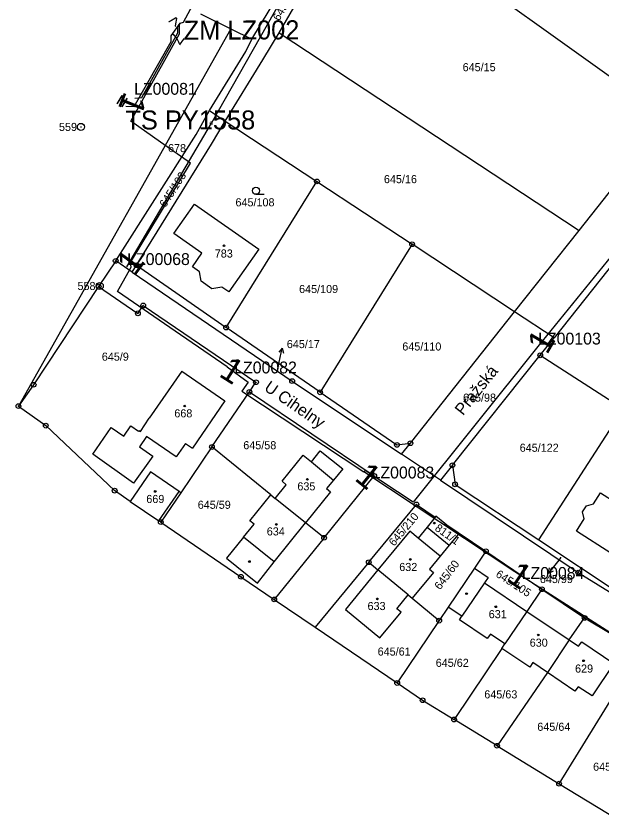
# Model space of a CAD drawing. Extents: x -738131 to -734179, y -1033447 to -1030078.
# Drawn here: x -736294.6 to -736171.2, y -1032867.6 to -1032698.6 of the extents above; entities that cross this region are included whole.
import ezdxf

# ---------------------------------------------------------------- set-up
doc = ezdxf.new("R2010")
doc.units = 0
for name, color, linetype in [('ftf_2010', 7, 'Continuous'), ('ftf_2050', 7, 'Continuous'), ('ftf_2060', 7, 'Continuous'), ('ftf_3010', 7, 'Continuous'), ('ftf_3010_ftf_3010_gtda_3015_gtda_3015_1', 7, 'Continuous'), ('ftf_3150', 7, 'Continuous'), ('ftf_3150_ftf_3150_gtda_3155_gtda_3155_1', 7, 'Continuous'), ('ftf_3160', 7, 'Continuous'), ('ftf_3160_ftf_3160_gtda_3165_gtda_3165_1', 7, 'Continuous'), ('ftf_3170', 7, 'Continuous'), ('ftf_3240', 7, 'Continuous'), ('ftf_nu', 7, 'Continuous'), ('Vrstva 1', 7, 'Continuous'), ('Vrstva 2', 7, 'Continuous'), ('Vrstva 3', 7, 'Continuous'), ('Vrstva 4', 7, 'Continuous'), ('Vrstva 5', 7, 'Continuous'), ('Vrstva 7', 7, 'Continuous'), ('Vrstva 8', 7, 'Continuous')]:
    doc.layers.add(name, color=color, linetype=linetype)

msp = doc.modelspace()

# ---------------------------------------------------------------- linework, layer by layer
at = {"layer": 'ftf_2010'}
for points in [[(-736260.08, -1032700.09), (-736259.36, -1032699.83), (-736255.9, -1032693.4)], [(-736250.19, -1032772.44), (-736261.12, -1032764.89), (-736273.29, -1032756.56), (-736270.36, -1032751.45), (-736270.49, -1032750.48), (-736257.9, -1032729.52), (-736264.19, -1032725.12), (-736270.47, -1032720.72), (-736260.17, -1032702.28), (-736260.17, -1032700.42), (-736260.08, -1032700.09)], [(-736269.58, -1032715.86), (-736268.12, -1032715.71), (-736260.53, -1032702.12), (-736260.53, -1032700.85), (-736260.08, -1032700.09)], [(-736167.34, -1032747.62), (-736168.31, -1032747.92), (-736184.73, -1032768.17)], [(-736184.73, -1032768.17), (-736210.99, -1032800.91), (-736221.08, -1032794.29), (-736221.41, -1032794.56)], [(-736250.19, -1032772.44), (-736245.76, -1032775.68), (-736247.06, -1032777.59), (-736221.41, -1032794.56)], [(-736189.57, -1032815.57), (-736221.41, -1032794.56)], [(-736158.51, -1032835.5), (-736189.57, -1032815.57)]]:
    msp.add_lwpolyline(points, dxfattribs=at)
at = {"layer": 'ftf_2050'}
msp.add_lwpolyline([(-736271.31, -1032751.37), (-736253.49, -1032721.14), (-736231.33, -1032682.11)], dxfattribs=at)
at = {"layer": 'ftf_2060'}
msp.add_lwpolyline([(-736271.48, -1032717.58), (-736269.72, -1032717.63), (-736261.98, -1032703.91), (-736261.98, -1032702.76), (-736260.08, -1032700.09)], dxfattribs=at)
at = {"layer": 'Vrstva 1'}
for points in [[(-736165.79, -1032714.02), (-736208.22, -1032683.61)], [(-736244.97, -1032703.43), (-736236.07, -1032688.6)], [(-736239.18, -1032702.09), (-736232.56, -1032690.52)], [(-736255.81, -1032698.1), (-736249.41, -1032701.25)], [(-736249.41, -1032701.25), (-736294.12, -1032780.7)], [(-736249.41, -1032701.25), (-736244.97, -1032703.43)], [(-736242.67, -1032707.79), (-736239.18, -1032702.09)], [(-736239.18, -1032702.09), (-736176.04, -1032743.72)], [(-736246.25, -1032706.01), (-736244.97, -1032703.43)], [(-736253.9, -1032718.47), (-736246.25, -1032706.01)], [(-736250.56, -1032720.67), (-736242.67, -1032707.79)], [(-736256.7, -1032723.54), (-736253.9, -1032718.47)], [(-736253.9, -1032718.47), (-736250.56, -1032720.67)], [(-736176.04, -1032743.72), (-736157.13, -1032719.88)], [(-736253.46, -1032725.57), (-736250.56, -1032720.67)], [(-736250.56, -1032720.67), (-736231.25, -1032733.4)], [(-736273.64, -1032750.13), (-736256.7, -1032723.54)], [(-736269.28, -1032751.04), (-736253.46, -1032725.57)], [(-736250.38, -1032764.16), (-736231.25, -1032733.4)], [(-736231.25, -1032733.4), (-736211.21, -1032746.61)], [(-736261.37, -1032744.38), (-736257.07, -1032738.2)], [(-736257.07, -1032738.2), (-736243.52, -1032747.65)], [(-736189.62, -1032760.85), (-736176.04, -1032743.72)], [(-736255.5, -1032748.53), (-736261.37, -1032744.38)], [(-736211.21, -1032746.61), (-736230.59, -1032777.8)], [(-736189.62, -1032760.85), (-736211.21, -1032746.61)], [(-736257.46, -1032751.37), (-736255.5, -1032748.53)], [(-736243.52, -1032747.65), (-736249.83, -1032756.67)], [(-736166.77, -1032748.02), (-736181.29, -1032766.34)], [(-736273.64, -1032750.13), (-736277.23, -1032755.55)], [(-736270.18, -1032752.49), (-736273.64, -1032750.13)], [(-736270.18, -1032752.49), (-736269.28, -1032751.04)], [(-736269.28, -1032751.04), (-736250.38, -1032764.16)], [(-736256.01, -1032752.41), (-736257.46, -1032751.37)], [(-736270.18, -1032752.49), (-736236.47, -1032775.43)], [(-736255.63, -1032754.37), (-736256.01, -1032752.41)], [(-736277.23, -1032755.55), (-736290.92, -1032776.2)], [(-736277.23, -1032755.55), (-736268.96, -1032761.17)], [(-736253.37, -1032756.03), (-736255.63, -1032754.37)], [(-736251.28, -1032755.68), (-736253.37, -1032756.03)], [(-736249.83, -1032756.67), (-736251.28, -1032755.68)], [(-736268.96, -1032761.17), (-736267.84, -1032759.52)], [(-736267.84, -1032759.52), (-736244.09, -1032775.68)], [(-736211.57, -1032788.52), (-736189.62, -1032760.85)], [(-736181.29, -1032766.34), (-736189.62, -1032760.85)], [(-736230.59, -1032777.8), (-736250.38, -1032764.16)], [(-736184.23, -1032770.01), (-736181.29, -1032766.34)], [(-736202.73, -1032793.15), (-736184.23, -1032770.01)], [(-736184.23, -1032770.01), (-736166.73, -1032781.27)], [(-736259.72, -1032773.32), (-736266.58, -1032783.25)], [(-736259.72, -1032773.32), (-736250.63, -1032779.62)], [(-736245.47, -1032777.71), (-736244.09, -1032775.68)], [(-736236.47, -1032775.43), (-736213.42, -1032790.86)], [(-736290.92, -1032776.2), (-736294.12, -1032780.7)], [(-736253.37, -1032789.31), (-736245.47, -1032777.71)], [(-736245.47, -1032777.71), (-736219.19, -1032795.42)], [(-736230.59, -1032777.8), (-736214.41, -1032788.87)], [(-736294.12, -1032780.7), (-736288.37, -1032784.82)], [(-736250.63, -1032779.62), (-736257.47, -1032789.55)], [(-736184.5, -1032808.88), (-736166.73, -1032781.27)], [(-736268.44, -1032786.06), (-736266.58, -1032783.25)], [(-736288.37, -1032784.82), (-736273.86, -1032798.51)], [(-736278.47, -1032790.81), (-736274.6, -1032785.18)], [(-736274.6, -1032785.18), (-736271.95, -1032787.02)], [(-736271.95, -1032787.02), (-736270.43, -1032784.85)], [(-736270.43, -1032784.85), (-736268.82, -1032785.97)], [(-736268.82, -1032785.97), (-736268.74, -1032785.85)], [(-736268.74, -1032785.85), (-736268.44, -1032786.06)], [(-736267.13, -1032787.11), (-736268.63, -1032789.3)], [(-736260.88, -1032791.42), (-736267.13, -1032787.11)], [(-736268.63, -1032789.3), (-736265.83, -1032791.26)], [(-736258.91, -1032788.55), (-736260.88, -1032791.42)], [(-736253.37, -1032789.31), (-736259.94, -1032798.96)], [(-736258.91, -1032788.55), (-736257.47, -1032789.55)], [(-736240.95, -1032799.39), (-736253.37, -1032789.31)], [(-736214.41, -1032788.87), (-736211.57, -1032788.52)], [(-736213.42, -1032790.86), (-736211.57, -1032788.52)], [(-736269.86, -1032796.9), (-736278.47, -1032790.81)], [(-736238.61, -1032796.51), (-736234.17, -1032791.02)], [(-736234.17, -1032791.02), (-736232.4, -1032792.45)], [(-736232.4, -1032792.45), (-736230.56, -1032790.12)], [(-736230.56, -1032790.12), (-736225.83, -1032793.9)], [(-736205.26, -1032796.31), (-736213.42, -1032790.86)], [(-736265.83, -1032791.26), (-736269.86, -1032796.9)], [(-736225.83, -1032793.9), (-736227.8, -1032796.27)], [(-736202.73, -1032793.15), (-736205.26, -1032796.31)], [(-736202.73, -1032793.15), (-736202.16, -1032797.18)], [(-736266.34, -1032794.56), (-736270.56, -1032800.76)], [(-736260.29, -1032798.72), (-736266.34, -1032794.56)], [(-736229.74, -1032808.44), (-736219.19, -1032795.42)], [(-736240.05, -1032800.14), (-736237.76, -1032797.28)], [(-736237.76, -1032797.28), (-736238.61, -1032796.51)], [(-736227.8, -1032796.27), (-736229.24, -1032798.05)], [(-736205.26, -1032796.31), (-736176.22, -1032815.75)], [(-736202.16, -1032797.18), (-736184.5, -1032808.88)], [(-736270.56, -1032800.76), (-736273.86, -1032798.51)], [(-736259.94, -1032798.96), (-736264.14, -1032805.13)], [(-736259.94, -1032798.96), (-736260.29, -1032798.72)], [(-736245.38, -1032804.86), (-736240.95, -1032799.39)], [(-736240.95, -1032799.39), (-736240.05, -1032800.14)], [(-736228.37, -1032798.78), (-736233.64, -1032805.31)], [(-736229.24, -1032798.05), (-736228.37, -1032798.78)], [(-736173.03, -1032801.32), (-736171.51, -1032798.95)], [(-736171.51, -1032798.95), (-736161.62, -1032805.31)], [(-736270.56, -1032800.76), (-736264.52, -1032804.87)], [(-736233.64, -1032805.31), (-736240.05, -1032800.14)], [(-736220.34, -1032813.59), (-736210.3, -1032801.41)], [(-736210.3, -1032801.41), (-736206.34, -1032804.08)], [(-736175.35, -1032802.97), (-736174.52, -1032801.69)], [(-736175.01, -1032804.46), (-736175.35, -1032802.97)], [(-736174.52, -1032801.69), (-736173.03, -1032801.32)], [(-736206.34, -1032804.08), (-736208.04, -1032806.17)], [(-736206.19, -1032803.89), (-736206.34, -1032804.08)], [(-736204.29, -1032805.46), (-736206.19, -1032803.89)], [(-736176.62, -1032807.01), (-736175.01, -1032804.46)], [(-736264.14, -1032805.13), (-736264.52, -1032804.87)], [(-736264.14, -1032805.13), (-736247.26, -1032816.64)], [(-736246.69, -1032808.31), (-736244.49, -1032805.54)], [(-736244.49, -1032805.54), (-736245.38, -1032804.86)], [(-736240.28, -1032813.52), (-736233.64, -1032805.31)], [(-736229.74, -1032808.44), (-736233.64, -1032805.31)], [(-736208.04, -1032806.17), (-736209.96, -1032808.49)], [(-736208.04, -1032806.17), (-736203.42, -1032810)], [(-736204.29, -1032805.46), (-736195.68, -1032811.26)], [(-736201.5, -1032807.75), (-736204.29, -1032805.46)], [(-736211.7, -1032807.05), (-736218.41, -1032815.19)], [(-736209.96, -1032808.49), (-736211.7, -1032807.05)], [(-736201.5, -1032807.75), (-736203.42, -1032810)], [(-736169.38, -1032811.7), (-736176.62, -1032807.01)], [(-736246.69, -1032808.31), (-736250.32, -1032812.71)], [(-736229.74, -1032808.44), (-736240.24, -1032821.41)], [(-736184.5, -1032808.88), (-736167.59, -1032820.09)], [(-736203.42, -1032810), (-736205.33, -1032812.32)], [(-736195.68, -1032811.26), (-736198.08, -1032814.82)], [(-736195.68, -1032811.26), (-736183.88, -1032819.26)], [(-736250.32, -1032812.71), (-736243.8, -1032817.97)], [(-736205.33, -1032812.32), (-736207.57, -1032815.01)], [(-736243.8, -1032817.97), (-736240.28, -1032813.52)], [(-736220.34, -1032813.59), (-736231.62, -1032827.27)], [(-736220.34, -1032813.59), (-736218.41, -1032815.19)], [(-736218.41, -1032815.19), (-736225.25, -1032823.54)], [(-736212.05, -1032820.46), (-736218.41, -1032815.19)], [(-736206.69, -1032815.74), (-736211.18, -1032821.18)], [(-736207.57, -1032815.01), (-736206.69, -1032815.74)], [(-736198.08, -1032814.82), (-736203.6, -1032823.03)], [(-736198.08, -1032814.82), (-736195.2, -1032816.77)], [(-736176.22, -1032815.75), (-736145.31, -1032834.85)], [(-736247.26, -1032816.64), (-736240.24, -1032821.41)], [(-736195.2, -1032816.77), (-736195.98, -1032817.92)], [(-736195.98, -1032817.92), (-736187.02, -1032823.93)], [(-736183.88, -1032819.26), (-736187.02, -1032823.93)], [(-736183.88, -1032819.26), (-736174.89, -1032825.31)], [(-736240.24, -1032821.41), (-736231.62, -1032827.27)], [(-736214.41, -1032823.38), (-736212.05, -1032820.46)], [(-736212.05, -1032820.46), (-736211.18, -1032821.18)], [(-736211.18, -1032821.18), (-736205.52, -1032825.88)], [(-736203.6, -1032823.03), (-736205.52, -1032825.88)], [(-736200.74, -1032824.97), (-736203.6, -1032823.03)], [(-736225.25, -1032823.54), (-736218.02, -1032829.51)], [(-736218.02, -1032829.51), (-736213.53, -1032824.07)], [(-736213.53, -1032824.07), (-736214.41, -1032823.38)], [(-736187.02, -1032823.93), (-736191.66, -1032830.79)], [(-736205.52, -1032825.88), (-736214.36, -1032839.01)], [(-736201.24, -1032825.7), (-736200.74, -1032824.97)], [(-736195.39, -1032829.64), (-736201.24, -1032825.7)], [(-736178.12, -1032829.93), (-736174.89, -1032825.31)], [(-736174.89, -1032825.31), (-736163.08, -1032832.36)], [(-736231.62, -1032827.27), (-736214.36, -1032839.01)], [(-736194.74, -1032828.72), (-736195.39, -1032829.64)], [(-736191.66, -1032830.79), (-736194.74, -1032828.72)], [(-736178.12, -1032829.93), (-736182.7, -1032836.79)], [(-736178.12, -1032829.93), (-736176.16, -1032831.24)], [(-736192.3, -1032831.73), (-736191.66, -1032830.79)], [(-736176.16, -1032831.24), (-736175.48, -1032830.31)], [(-736175.48, -1032830.31), (-736168.72, -1032834.88)], [(-736192.3, -1032831.73), (-736202.38, -1032846.7)], [(-736186.44, -1032835.66), (-736192.3, -1032831.73)], [(-736180.26, -1032860.22), (-736163.08, -1032832.36)], [(-736185.79, -1032834.71), (-736186.44, -1032835.66)], [(-736182.7, -1032836.79), (-736185.79, -1032834.71)], [(-736168.72, -1032834.88), (-736173.32, -1032841.73)], [(-736182.7, -1032836.79), (-736193.33, -1032852.23)], [(-736176.92, -1032840.74), (-736182.7, -1032836.79)], [(-736214.36, -1032839.01), (-736209, -1032842.65)], [(-736176.24, -1032839.81), (-736176.92, -1032840.74)], [(-736173.32, -1032841.73), (-736176.24, -1032839.81)], [(-736209, -1032842.65), (-736202.38, -1032846.7)], [(-736193.33, -1032852.23), (-736202.38, -1032846.7)], [(-736193.33, -1032852.23), (-736180.26, -1032860.22)], [(-736180.26, -1032860.22), (-736168.12, -1032867.64)]]:
    msp.add_lwpolyline(points, dxfattribs=at)
at = {"layer": 'Vrstva 3'}
msp.add_line((-736244.09, -1032736.1), (-736242.34, -1032736.1), dxfattribs=at)
msp.add_circle((-736244.09, -1032735.35), 0.75, dxfattribs=at)
at = {"layer": 'Vrstva 4'}
for points in [[(-736232.4, -1032792.45), (-736227.8, -1032796.27)], [(-736264.52, -1032804.87), (-736260.29, -1032798.72)], [(-736240.28, -1032813.52), (-736246.69, -1032808.31)], [(-736205.33, -1032812.32), (-736209.96, -1032808.49)], [(-736195.98, -1032817.92), (-736200.74, -1032824.97)], [(-736187.02, -1032823.93), (-736178.12, -1032829.93)]]:
    msp.add_lwpolyline(points, dxfattribs=at)
at = {"layer": 'Vrstva 5'}
for centre in [(-736250.82, -1032746.95), (-736259.1, -1032780.69), (-736233.27, -1032796.13), (-736265.31, -1032798.67), (-736239.82, -1032805.62), (-736206.54, -1032805.35), (-736211.59, -1032813), (-736245.47, -1032813.44), (-736218.53, -1032821.3), (-736199.75, -1032820.2), (-736193.6, -1032822.96), (-736184.64, -1032828.89), (-736175.12, -1032834.34)]:
    msp.add_circle(centre, 0.175, dxfattribs=at)
at = {"layer": 'Vrstva 7'}
for p, q in [((-736238.6, -1032768.49), (-736239.29, -1032769.37)), ((-736239.19, -1032771.43), (-736238.6, -1032768.49)), ((-736238.6, -1032768.49), (-736238.31, -1032769.57)), ((-736180.61, -1032813.51), (-736182.49, -1032815.85)), ((-736182.49, -1032815.85), (-736182.25, -1032814.76)), ((-736182.49, -1032815.85), (-736181.47, -1032815.38))]:
    msp.add_line(p, q, dxfattribs=at)
for points in [[(-736239.39, -1032772.45), (-736239.19, -1032771.43)], [(-736179.86, -1032812.57), (-736180.61, -1032813.51)]]:
    msp.add_lwpolyline(points, dxfattribs=at)
at = {"layer": 'Vrstva 8'}
for centre, radius in [((-736280.96, -1032721.92), 0.75), ((-736280.96, -1032721.92), 0.03), ((-736231.25, -1032733.4), 0.5), ((-736231.25, -1032733.4), 0.0303), ((-736211.21, -1032746.61), 0.5), ((-736211.21, -1032746.61), 0.0303), ((-736273.64, -1032750.13), 0.5), ((-736273.64, -1032750.13), 0.0303), ((-736269.28, -1032751.04), 0.5), ((-736269.28, -1032751.04), 0.0303), ((-736277, -1032755.41), 0.75), ((-736277.23, -1032755.55), 0.5), ((-736277.23, -1032755.55), 0.0303), ((-736277, -1032755.41), 0.03), ((-736267.84, -1032759.52), 0.5), ((-736268.96, -1032761.17), 0.5), ((-736267.84, -1032759.52), 0.0303), ((-736268.96, -1032761.17), 0.0303), ((-736250.38, -1032764.16), 0.5), ((-736250.38, -1032764.16), 0.0303), ((-736184.23, -1032770.01), 0.5), ((-736184.23, -1032770.01), 0.0303), ((-736290.92, -1032776.2), 0.5), ((-736244.09, -1032775.68), 0.5), ((-736244.09, -1032775.68), 0.0303), ((-736236.47, -1032775.43), 0.5), ((-736236.47, -1032775.43), 0.0303), ((-736290.92, -1032776.2), 0.0303), ((-736245.47, -1032777.71), 0.5), ((-736230.59, -1032777.8), 0.5), ((-736245.47, -1032777.71), 0.0303), ((-736230.59, -1032777.8), 0.0303), ((-736294.12, -1032780.7), 0.5), ((-736294.12, -1032780.7), 0.0303), ((-736288.37, -1032784.82), 0.5), ((-736288.37, -1032784.82), 0.0303), ((-736253.37, -1032789.31), 0.5), ((-736253.37, -1032789.31), 0.0303), ((-736214.41, -1032788.87), 0.5), ((-736214.41, -1032788.87), 0.0303), ((-736211.57, -1032788.52), 0.5), ((-736211.57, -1032788.52), 0.0303), ((-736202.73, -1032793.15), 0.5), ((-736202.73, -1032793.15), 0.0303), ((-736219.19, -1032795.42), 0.5), ((-736219.19, -1032795.42), 0.0303), ((-736202.16, -1032797.18), 0.5), ((-736202.16, -1032797.18), 0.0303), ((-736273.86, -1032798.51), 0.5), ((-736273.86, -1032798.51), 0.0303), ((-736210.3, -1032801.41), 0.5), ((-736210.3, -1032801.41), 0.0303), ((-736264.14, -1032805.13), 0.5), ((-736264.14, -1032805.13), 0.0303), ((-736229.74, -1032808.44), 0.5), ((-736229.74, -1032808.44), 0.0303), ((-736195.68, -1032811.26), 0.5), ((-736195.68, -1032811.26), 0.0303), ((-736220.34, -1032813.59), 0.5), ((-736220.34, -1032813.59), 0.0303), ((-736247.26, -1032816.64), 0.5), ((-736176.22, -1032815.75), 0.5), ((-736176.22, -1032815.75), 0.0303), ((-736247.26, -1032816.64), 0.0303), ((-736183.88, -1032819.26), 0.5), ((-736183.88, -1032819.26), 0.0303), ((-736240.24, -1032821.41), 0.5), ((-736240.24, -1032821.41), 0.0303), ((-736174.89, -1032825.31), 0.5), ((-736205.52, -1032825.88), 0.5), ((-736205.52, -1032825.88), 0.0303), ((-736174.89, -1032825.31), 0.0303), ((-736214.36, -1032839.01), 0.5), ((-736214.36, -1032839.01), 0.0303), ((-736209, -1032842.65), 0.5), ((-736209, -1032842.65), 0.0303), ((-736202.38, -1032846.7), 0.5), ((-736202.38, -1032846.7), 0.0303), ((-736193.33, -1032852.23), 0.5), ((-736193.33, -1032852.23), 0.0303), ((-736180.26, -1032860.22), 0.5), ((-736180.26, -1032860.22), 0.0303)]:
    msp.add_circle(centre, radius, dxfattribs=at)

# ---------------------------------------------------------------- texts
at = {"layer": 'ftf_3010'}
for rotation, p in [(248.0218, (-736271.74, -1032714.29)), (53.6094, (-736269.6, -1032753.43)), (59.7629, (-736182.81, -1032770.04)), (327.7961, (-736252.12, -1032774.3)), (321.1571, (-736223.54, -1032796.18)), (326.1679, (-736191.55, -1032817.37))]:
    msp.add_text('1', height=5.2, rotation=rotation, dxfattribs=at).set_placement(p)
at = {"layer": 'ftf_3010_ftf_3010_gtda_3015_gtda_3015_1'}
for s, p in [('LZ00081', (-736269.76, -1032715.14)), ('LZ00068', (-736271.22, -1032751)), ('LZ00103', (-736184.68, -1032767.74))]:
    msp.add_text(s, height=2.5, rotation=0, dxfattribs=at).set_placement(p)
for s, p in [('LZ00082', (-736248.68, -1032773.82)), ('LZ00083', (-736219.75, -1032795.94)), ('LZ00084', (-736188.13, -1032817.09))]:
    msp.add_text(s, height=2.5, dxfattribs=at).set_placement(p)
at = {"layer": 'ftf_3150'}
msp.add_text('>', height=2.7, rotation=55.4557, dxfattribs=at).set_placement((-736260.84, -1032701.2))
at = {"layer": 'ftf_3150_ftf_3150_gtda_3155_gtda_3155_1'}
msp.add_text('ZM LZ002', height=4, rotation=0.2392, dxfattribs=at).set_placement((-736259.32, -1032703.56))
at = {"layer": 'ftf_3160'}
msp.add_text('=', height=3.3, rotation=238.4712, dxfattribs=at).set_placement((-736272.96, -1032714.54))
at = {"layer": 'ftf_3160_ftf_3160_gtda_3165_gtda_3165_1'}
msp.add_text('TS PY1558', height=4, rotation=0.0326, dxfattribs=at).set_placement((-736271.6, -1032722.46))
at = {"layer": 'ftf_3170'}
msp.add_text('7', height=2.7, rotation=234.382, dxfattribs=at).set_placement((-736261.2, -1032701.66))
at = {"layer": 'ftf_3240'}
msp.add_text('G', height=0.8, dxfattribs=at).set_placement((-736253.89, -1032721.54))
at = {"layer": 'ftf_nu'}
for s, rotation, p in [('Pražská', 51.4792, (-736200.49, -1032782.84)), ('U Cihelny', 325.3236, (-736242.55, -1032777.27))]:
    msp.add_text(s, height=2.5, rotation=rotation, dxfattribs=at).set_placement(p)
at = {"layer": 'Vrstva 2'}
for s, rotation, p in [('645/14', 59.5984, (-736239.21, -1032699.72)), ('645/103', 57.1886, (-736263.15, -1032739.02)), ('645/210', 50.0002, (-736214.99, -1032810.33)), ('811/1', 324.713, (-736206.58, -1032806.75)), ('645/60', 53.1085, (-736205.32, -1032819.52)), ('645/105', 327.046, (-736193.76, -1032816.5))]:
    msp.add_text(s, height=1.7, rotation=rotation, dxfattribs=at).set_placement(p)
for s, height, p in [('645/15', 1.7, (-736200.57, -1032710.19)), ('678', 1.7, (-736262.62, -1032727.22)), ('645/16', 1.7, (-736217.15, -1032733.76)), ('645/108', 1.7, (-736248.41, -1032738.64)), ('783', 1.7, (-736252.77, -1032749.42)), ('645/109', 1.7, (-736235.02, -1032756.9)), ('645/110', 1.7, (-736213.28, -1032769)), ('645/9', 1.7, (-736276.56, -1032771.14)), ('645/17', 0.1, (-736239.59, -1032772.45)), ('645/98', 1.7, (-736200.5, -1032779.77)), ('668', 1.7, (-736261.29, -1032783.08)), ('645/58', 1.7, (-736246.77, -1032789.79)), ('645/122', 1.7, (-736188.56, -1032790.32)), ('635', 1.7, (-736235.38, -1032798.45)), ('669', 1.7, (-736267.19, -1032801.11)), ('645/59', 1.7, (-736256.36, -1032802.33)), ('634', 1.7, (-736241.82, -1032807.94)), ('645/99', 0.1, (-736180.08, -1032812.57)), ('632', 1.7, (-736213.92, -1032815.43)), ('633', 1.7, (-736220.6, -1032823.66)), ('631', 1.7, (-736195.08, -1032825.37)), ('630', 1.7, (-736186.45, -1032831.37)), ('645/61', 1.7, (-736218.47, -1032833.24)), ('645/62', 1.7, (-736206.24, -1032835.61)), ('629', 1.7, (-736176.9, -1032836.82)), ('645/63', 1.7, (-736196.01, -1032842.26)), ('645/64', 1.7, (-736184.85, -1032849.08)), ('645/65', 1.7, (-736173.1, -1032857.49))]:
    msp.add_text(s, height=height, dxfattribs=at).set_placement(p)
at = {"layer": 'Vrstva 7'}
for s, p in [('645/17', (-736237.6, -1032768.49)), ('645/99', (-736184.31, -1032817.97))]:
    msp.add_text(s, height=1.7, dxfattribs=at).set_placement(p)
at = {"layer": 'Vrstva 8'}
for s, p in [('559', (-736285.58, -1032722.77)), ('558', (-736281.68, -1032756.26))]:
    msp.add_text(s, height=1.7, dxfattribs=at).set_placement(p)

doc.saveas('drawing.dxf')
